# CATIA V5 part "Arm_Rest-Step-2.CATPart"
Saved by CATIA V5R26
Part number: Arm_Rest
Bounding box of the stored display mesh (mm): x 764.645 to 1406.698, y -782.252 to -669.463, z 394.638 to 524.862
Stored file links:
  D:\LinkedIn Learning\NURBS\CATIA\Class Parts\Arm_Rest-Step-2.CATPart
  D:\LinkedIn Learning\NURBS\Arm_Rest.CATPart
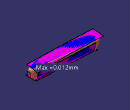
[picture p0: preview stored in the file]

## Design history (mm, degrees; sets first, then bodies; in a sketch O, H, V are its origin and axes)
AxisSystem1: origin (0, 0, 0), X (1, 0, 0), Y (0, 1, 0), Z (0, 0, 1)
StDynAnalysisRootNodeFeature1 "CATStDynAnalysisRootNodeName"
Set1 "REF DATA"
  CLDGeom1 "TOP"
  CLDGeom2 "FRONT"
  CLDGeom3 "AFT_BLEND"
  CLDGeom4 "END_AFT"
  CLDGeom5 "FORWARD_BLEND"
  CLDGeom6 "BOTTOM"
  CLDGeom7 "END_FORWARD"
  CLDGeom8 "UPPER_BLENDS"
  CLDGeom9 "LOWER_BLENDS"
  DatumSurface1 "DOOR_TRIM_SURFACE"
Set2 "FORM"
  Set3 "SLABS"
    DatumSurface2 to DatumSurface6
Body1 (main body)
